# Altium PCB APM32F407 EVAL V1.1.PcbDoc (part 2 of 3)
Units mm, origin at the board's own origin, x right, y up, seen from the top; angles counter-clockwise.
Board outline 133.48 x 125.98 mm, 2 copper layers (Top Layer, Bottom Layer); 143 components, 208 nets, 809 pads, 486 vias.
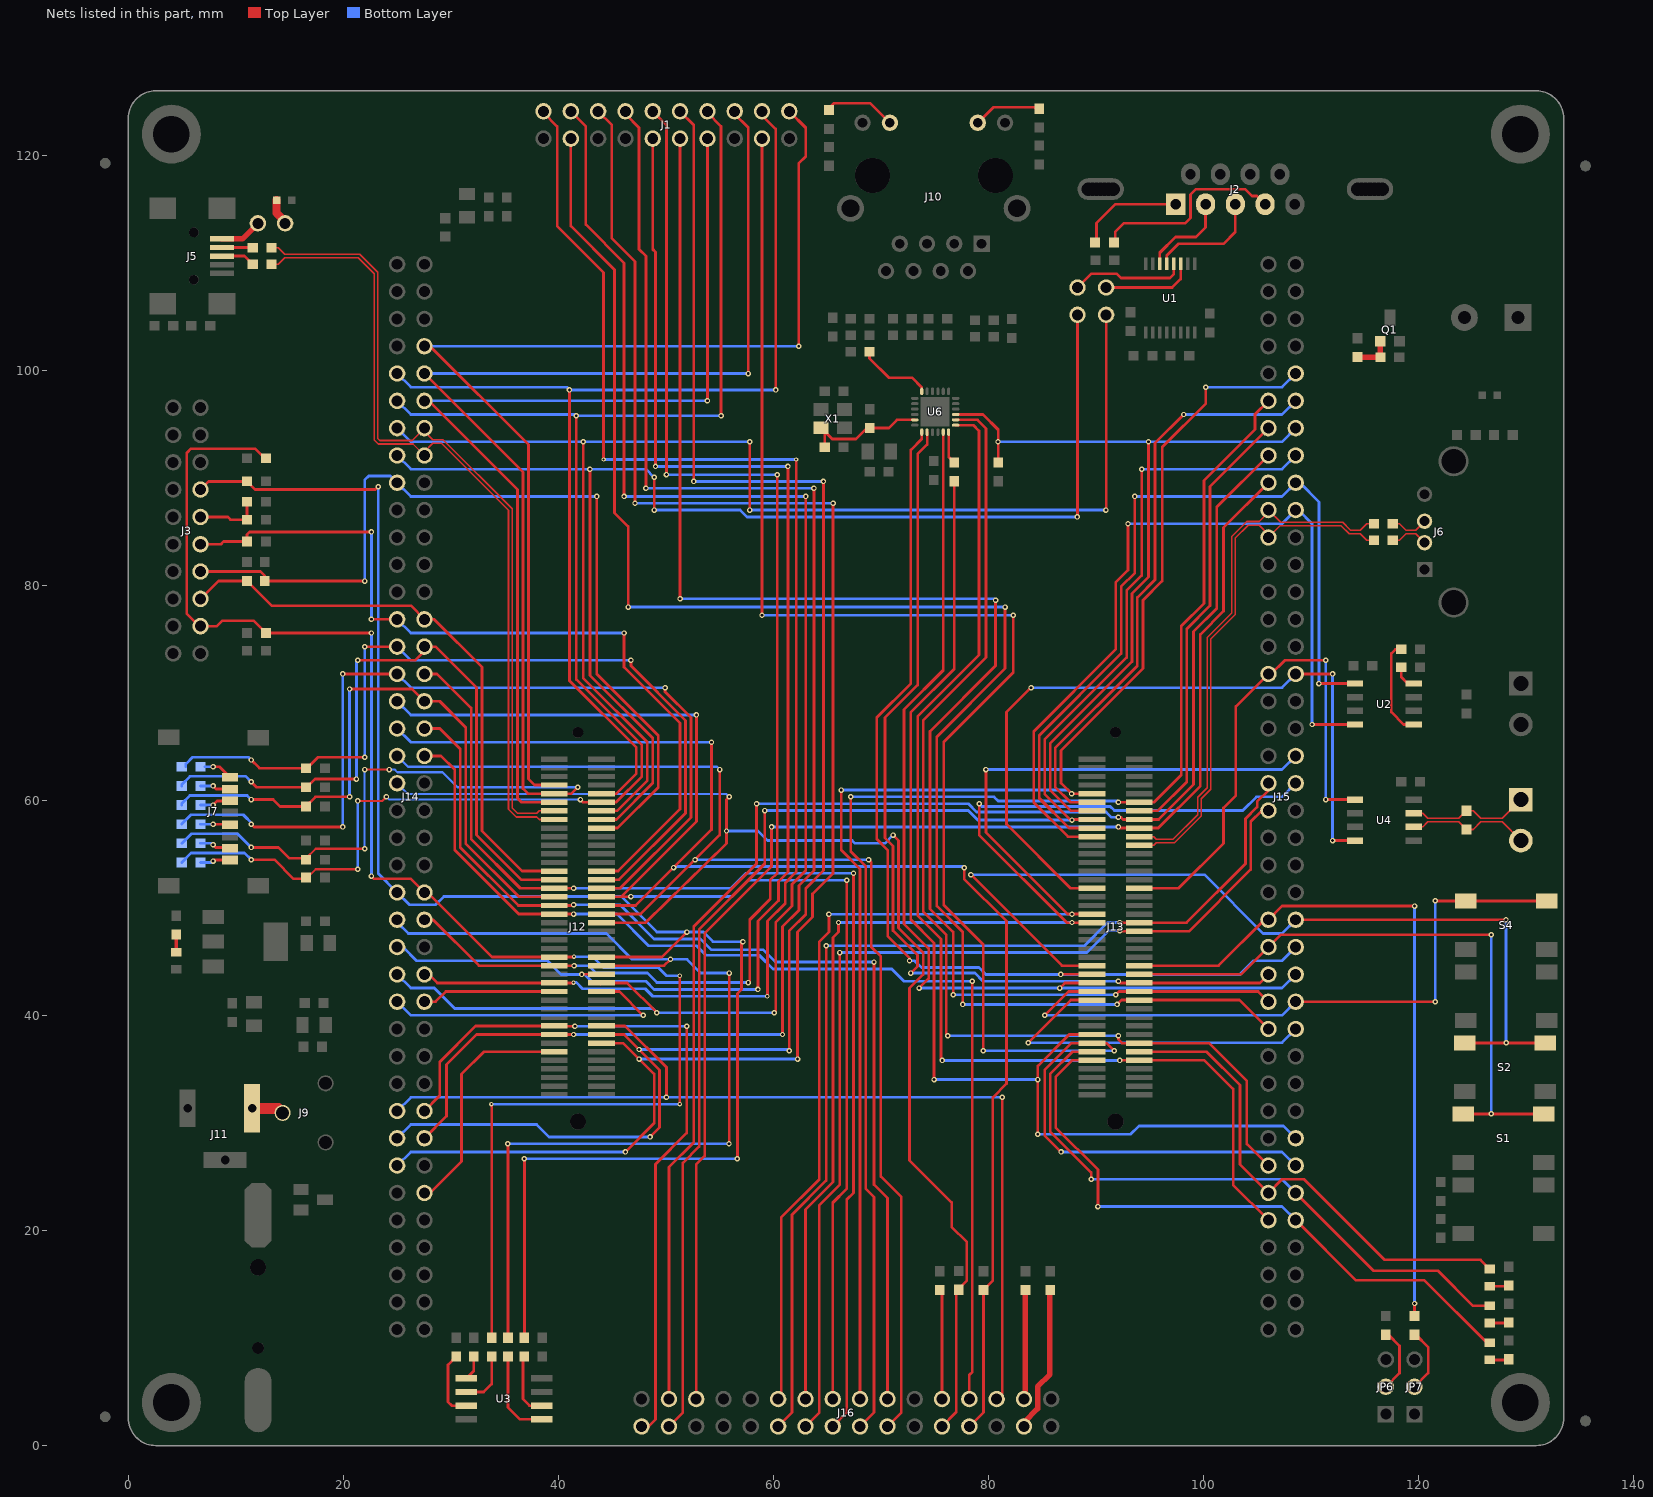
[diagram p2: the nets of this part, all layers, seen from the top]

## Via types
v1: diameter 0.508, hole 0.254, Top Layer to Bottom Layer, 294 vias
v2: diameter 0.61, hole 0.305, Top Layer to Bottom Layer, 172 vias
v3: diameter 0.406, hole 0.203, Top Layer to Bottom Layer, 17 vias
v4: diameter 0.6, hole 0.3, Top Layer to Bottom Layer, 3 vias

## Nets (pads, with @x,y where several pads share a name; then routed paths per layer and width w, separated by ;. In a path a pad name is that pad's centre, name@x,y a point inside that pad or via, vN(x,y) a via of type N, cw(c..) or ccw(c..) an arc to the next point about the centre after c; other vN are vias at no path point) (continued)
NetC32_2: C32.2 R40.1 U6.5 X1.3 | length 10.9
  Top Layer w0.254: C32.2@64.76,92.837 64.76,94.302 65.463,93.599 67.667,93.599 68.697,94.629 R40.1@68.937,94.629 70.729,94.629 71.489,95.389 U6.5@73.133,95.389
NetD1_1: D1.1 R59.2 | length 1.6
  Top Layer w0.3: D1.1@4.445,45.885 R59.2@4.445,47.512
NetD2_1: D2.1 JP1.1 | length 2.5
  Top Layer w0.762: D2.1@13.778,115.824 13.778,114.619 14.581,113.816 JP1.1@14.581,113.665
NetD4_1: D4.1 R23.2 | length 1.8
  Top Layer w0.254: D4.1@126.595,11.392 128.321,11.392 R23.2@128.373,11.444
NetD5_1: D5.1 R24.2 | length 1.8
  Top Layer w0.254: D5.1@126.595,14.821 128.321,14.821 R24.2@128.373,14.873
NetD6_1: D6.1 R22.2 | length 1.8
  Top Layer w0.254: D6.1@126.595,7.963 128.321,7.963 R22.2@128.373,8.015
NetJ2_1: J2.1 R8.1 | length 9.9
  Top Layer w0.254: R8.1@90.033,111.887 90.033,113.679 91.797,115.443 J2.1@97.409,115.443
NetJ2_4: J2.4 R8.2 | length 18.4
  Top Layer w0.254: R8.2@91.783,111.887 91.783,112.889 92.559,113.665 98.274,113.665 98.782,114.173 98.782,116.332 99.29,116.84 103.862,116.84 104.497,116.205 104.953,116.205 J2.4@105.715,115.443
NetJ3_11: J3.11 R5.1 R21.2 | length 6.1
  Top Layer w0.254: J3.11@6.707,86.36 9.247,86.36 9.501,86.106 R21.2@11.039,86.106 R5.1@11.039,87.757
NetJ5_1: J5.1 JP1.2 | length 3.9
  Top Layer w0.508: J5.1@8.695,112.217 10.593,112.217 JP1.2@12.041,113.665
NetJ5_2: J5.2 R45.2 | length 2.9
  Top Layer w0.254: J5.2@8.695,111.417 11.533,111.417 R45.2@11.571,111.379
NetJ5_3: J5.3 R49.2 | length 3.2
  Top Layer w0.254: J5.3@8.695,110.617 10.809,110.617 R49.2@11.571,109.855
NetJ6_2: J6.2 R7.2 | length 3.6
  Top Layer w0.152: R7.2@117.588,84.201 118.213,84.201 118.81,84.798 119.711,84.798 J6.2@120.546,83.963
NetJ6_3: J6.3 R14.2 | length 3.6
  Top Layer w0.152: R14.2@117.588,85.725 118.213,85.725 118.81,85.128 119.711,85.128 J6.3@120.546,85.963
NetJ7_1: J7.1 R55.1 | length 2.8
  Top Layer w0.254: v1(7.874,63.119) 8.496,63.119 J7.1@9.465,62.15
  Bottom Layer w0.254: R55.1@7.098,63.119 v1(7.874,63.119)
NetJ7_2: J7.2 R48.1 | length 2.9
  Top Layer w0.254: v1(7.874,61.341) 8.165,61.05 J7.2@9.465,61.05
  Bottom Layer w0.254: R48.1@6.717,61.341 v1(7.874,61.341)
NetJ7_3: J7.3 R57.1 | length 2.9
  Top Layer w0.254: v1(7.874,59.563) 8.261,59.95 J7.3@9.465,59.95
  Bottom Layer w0.254: R57.1@6.717,59.563 v1(7.874,59.563)
NetJ7_5: J7.5 R56.1 | length 2.8
  Top Layer w0.254: v1(7.874,57.785) 9.43,57.785 J7.5@9.465,57.75
  Bottom Layer w0.254: R56.1@6.717,57.785 v1(7.874,57.785)
NetJ7_7: J7.7 R10.1 | length 2.9
  Top Layer w0.254: v1(7.874,55.88) 8.128,55.626 9.389,55.626 J7.7@9.465,55.55
  Bottom Layer w0.254: R10.1@6.717,56.007 7.747,56.007 v1(7.874,55.88)
NetJ7_8: J7.8 R19.1 | length 2.8
  Top Layer w0.254: v1(7.874,54.356) 7.968,54.45 J7.8@9.465,54.45
  Bottom Layer w0.254: R19.1@6.717,54.229 7.747,54.229 v1(7.874,54.356)
NetJ8_1: J8.1 R27.1 U4.7 | length 11.5
  Top Layer w0.152: U4.7@119.541,58.801 120.372,58.801 120.842,58.331 123.726,58.331 R27.1@124.436,59.041 125.071,59.041 125.781,58.331 127.76,58.331 J8.1@129.5,60.071
NetJ8_2: J8.2 R27.2 U4.6 | length 11.5
  Top Layer w0.152: U4.6@119.541,57.531 120.372,57.531 120.842,58.001 123.726,58.001 R27.2@124.436,57.291 125.071,57.291 125.781,58.001 127.76,58.001 J8.2@129.5,56.261
NetJ9_1: J9.1 J11.4 | length 3
  Top Layer w1.016: J11.4@11.509,31.356 13.936,31.356 J9.1@14.351,30.941
NetJ10_10: J10.10 R37.1 | length 6.3
  Top Layer w0.254: J10.10@78.991,123.01 80.441,124.46 84.29,124.46 R37.1@84.558,124.192
NetJ10_11: J10.11 R38.1 | length 7
  Top Layer w0.254: R38.1@64.873,124.065 65.649,124.841 68.99,124.841 J10.11@70.821,123.01
NetJ16_23: J16.23 R44.2 | length 10.2
  Top Layer w0.254: R44.2@75.462,14.467 75.668,14.261 J16.23@75.668,4.318
NetJ16_29: J16.29 R46.2 | length 10.2
  Top Layer w0.508: J16.29@83.288,4.318 83.415,4.445 83.415,14.443 R46.2@83.439,14.467
NetJ16_30: J16.30 R47.1 | length 13.7
  Top Layer w0.508: J16.30@83.288,1.778 83.288,2.159 84.558,3.429 84.558,5.475 85.701,6.618 85.701,14.443 R47.1@85.725,14.467
NetJP4_1: JP4.1 U1.11 | length 8.7
  Top Layer w0.254: JP4.1@90.932,107.696 97.075,107.696 97.865,108.486 U1.11@97.865,109.905
NetJP5_1: JP5.1 U1.12 | length 10.8
  Top Layer w0.254: JP5.1@88.265,107.696 89.535,108.966 91.924,108.966 92.305,108.585 96.877,108.585 97.215,108.923 U1.12@97.215,109.905
NetJP6_2: JP6.2 R61.1 | length 6
  Top Layer w0.254: JP6.2@116.943,5.461 118.213,6.731 118.213,9.271 117.183,10.301 R61.1@116.943,10.301
NetJP7_2: JP7.2 R62.1 | length 6
  Top Layer w0.254: JP7.2@119.61,5.461 120.88,6.731 120.88,9.144 119.723,10.301 R62.1@119.61,10.301
NetQ1_B: Q1.B R25.1 R28.2 | length 3.6
  Top Layer w0.508: R25.1@114.3,101.233 114.314,101.219 R28.2@116.449,101.219 116.424,101.244 Q1.B@116.424,102.686
NetR9_1: R9.1 U3.3 | length 6.4
  Top Layer w0.254: R9.1@30.48,8.269 29.718,7.507 29.718,4.064 30.075,3.707 U3.3@31.425,3.707
NetR11_2: R11.2 U2.5 | length 9.1
  Top Layer w0.254: R11.2@118.378,74.041 117.832,74.041 117.451,73.66 117.451,68.199 118.594,67.056 U2.5@119.541,67.056
NetR12_1: R12.1 U3.5 | length 8.3
  Top Layer w0.254: R12.1@35.306,8.269 35.306,3.556 36.425,2.437 U3.5@38.425,2.437
NetR15_2: R15.2 U3.2 | length 5.2
  Top Layer w0.254: U3.2@31.425,4.977 33.044,4.977 33.782,5.715 R15.2@33.782,8.269
NetR16_1: R16.1 U3.1 | length 2.3
  Top Layer w0.254: U3.1@31.425,6.247 32.131,6.953 R16.1@32.131,8.269
NetR17_1: R17.1 U3.6 | length 6
  Top Layer w0.254: R17.1@36.83,8.269 36.703,8.142 36.703,4.318 37.314,3.707 U3.6@38.425,3.707
NetR18_2: R18.2 U2.8 | length 2.3
  Top Layer w0.254: R18.2@118.378,72.39 118.378,71.463 118.975,70.866 U2.8@119.541,70.866
NetR30_1: R30.1 U6.12 | length 3
  Top Layer w0.254: U6.12@76.283,94.239 76.283,91.954 R30.1@76.811,91.426
NetR41_1: R41.1 U6.24 | length 7
  Top Layer w0.254: R41.1@68.923,101.727 68.923,101.106 70.715,99.314 72.874,99.314 73.783,98.405 U6.24@73.783,98.039
PA0_CAMRE_PW: J1.3 J13.68 J15.68 | length 163
  Top Layer w0.254: v1(58.928,77.216) J1.3@58.928,121.539 ; v1(79.502,36.703) 79.502,46.609 75.819,50.292 75.819,65.405 82.296,71.882 v1(82.296,77.216) ; v1(86.741,27.305) 85.217,28.829 85.217,34.925 87.716,37.424 J13.68@89.605,37.424 90.973,37.424 v1(91.694,36.703)
  Bottom Layer w0.254: v1(58.928,77.216) v1(82.296,77.216) ; v1(79.502,36.703) v1(91.694,36.703) ; v1(86.741,27.305) 107.291,27.305 J15.68@108.561,26.035
PA1_RMII_REF_CLK: J13.67 J15.67 U6.14 | length 101.5
  Top Layer w0.254: v1(76.2,38.1) 76.073,38.227 76.073,47.498 73.914,49.657 73.914,67.437 79.756,73.279 79.756,94.591 78.958,95.389 U6.14@76.933,95.389 ; v1(92.075,38.1) 92.075,37.763 92.415,37.424 J13.67@94.005,37.424 100.498,37.424 104.013,33.909 104.013,28.043 J15.67@106.021,26.035
  Bottom Layer w0.254: v1(76.2,38.1) v1(92.075,38.1)
PA2_ETH_MDIO: J13.66 J15.66 R30.2 | length 105.2
  Top Layer w0.254: v1(74.93,34.036) 74.93,46.736 72.771,48.895 72.771,68.199 76.811,72.239 R30.2@76.811,89.676 ; v1(84.582,28.956) v1(84.582,34.036) 84.582,35.306 87.5,38.224 J13.66@89.605,38.224
  Bottom Layer w0.254: v1(74.93,34.036) v1(84.582,34.036) ; v1(84.582,28.956) 93.218,28.956 93.98,29.718 107.418,29.718 J15.66@108.561,28.575
PA3_SDR_CKE: J13.58 J15.58 | length 32.9
  Top Layer w0.254: v1(83.693,37.465) 87.652,41.424 J13.58@89.605,41.424
  Bottom Layer w0.254: v1(83.693,37.465) 107.291,37.465 J15.58@108.561,38.735
PA4_DCMI_HS: J1.17 J13.57 J15.57 | length 151.1
  Top Layer w0.254: J1.17@41.148,121.539 41.148,113.411 45.212,109.347 45.212,86.741 46.482,85.471 v1(46.482,77.978) ; v1(77.597,41.021) 77.597,47.752 75.184,50.165 75.184,65.913 81.534,72.263 v1(81.534,77.978) ; v1(91.948,41.021) 92.351,41.424 J13.57@94.005,41.424 103.332,41.424 J15.57@106.021,38.735
  Bottom Layer w0.254: v1(46.482,77.978) v1(81.534,77.978) ; v1(77.597,41.021) v1(91.948,41.021)
PA5_KEY4: J13.56 J15.56 S4.3 S4.4 | length 61.9
  Top Layer w0.254: v1(85.217,40.005) 87.436,42.224 J13.56@89.605,42.224 ; J15.56@108.561,41.275 v1(121.539,41.275) ; v1(121.539,50.673) 121.575,50.637 S4.4@124.393,50.637 S4.3@131.893,50.637
  Bottom Layer w0.254: v1(85.217,40.005) 107.291,40.005 J15.56@108.561,41.275 ; v1(121.539,41.275) v1(121.539,50.673)
PA6_DCMI_PIXCK: J1.9 J13.55 J15.55 | length 142.1
  Top Layer w0.254: v1(51.308,78.74) J1.9@51.308,121.539 ; v1(76.708,41.91) 76.708,47.752 74.549,49.911 74.549,66.421 80.645,72.517 v1(80.645,78.613) ; v1(91.821,41.91) 92.135,42.224 J13.55@94.005,42.224 105.072,42.224 J15.55@106.021,41.275
  Bottom Layer w0.254: v1(51.308,78.74) 80.518,78.74 v1(80.645,78.613) ; v1(76.708,41.91) v1(91.821,41.91)
PA7_RMII_CRS_DV: J13.54 J15.54 U6.11 | length 93.3
  Top Layer w0.254: v1(73.533,42.545) 74.422,43.434 74.422,46.228 72.136,48.514 72.136,68.453 75.783,72.1 U6.11@75.783,94.239 ; v1(86.614,42.545) 87.093,43.024 J13.54@89.605,43.024
  Bottom Layer w0.254: v1(73.533,42.545) v1(86.614,42.545) 107.291,42.545 J15.54@108.561,43.815
PA8_CAMER_XCLK: J1.7 J12.12 J14.12 | length 95
  Top Layer w0.254: J14.12@27.535,97.155 27.94,97.155 36.195,88.9 36.195,60.198 36.569,59.824 J12.12@39.605,59.824 ; v1(53.848,97.155) J1.7@53.848,121.539
  Bottom Layer w0.254: J14.12@27.535,97.155 v1(53.848,97.155)
PA9_USART1_TX: J12.13 J14.13 JP4.2 | length 130.4
  Top Layer w0.254: v1(42.291,93.345) 42.291,71.374 48.26,65.405 48.26,61.849 45.435,59.024 J12.13@44.005,59.024 ; v1(57.785,86.995) v1(57.785,93.345) ; v1(90.908,86.995) 90.932,87.019 JP4.2@90.932,105.156
  Bottom Layer w0.254: J14.13@24.995,94.615 26.265,93.345 v1(42.291,93.345) v1(57.785,93.345) ; v1(57.785,86.995) v1(90.908,86.995)
PA10_USART1_RX: J12.15 J14.15 JP5.2 | length 124
  Top Layer w0.254: v1(42.926,90.805) 42.926,71.628 48.768,65.786 48.768,61.595 45.397,58.224 J12.15@44.005,58.224 ; v1(48.895,86.995) v1(48.895,90.043) ; v1(88.241,86.36) 88.265,86.384 JP5.2@88.265,105.156
  Bottom Layer w0.254: J14.15@24.995,92.075 26.265,90.805 v1(42.926,90.805) 48.133,90.805 v1(48.895,90.043) ; v1(48.895,86.995) 56.896,86.995 57.531,86.36 v1(88.241,86.36)
PA11_OTG_FS_N: J12.14 J14.14 R45.1 | length 74.6
  Top Layer w0.152: R45.1@13.321,111.379 13.946,111.379 14.543,110.782 21.511,110.782 23.19,109.103 23.19,93.65 23.368,93.472 26.392,93.472 J14.14@27.535,94.615 27.535,94.334 28.321,93.548 29.261,93.548 35.687,87.122 35.687,59.297 36.195,58.789 37.968,58.789 38.203,59.024 J12.14@39.605,59.024
PA12_OTG_FS_P: J12.16 J14.16 R49.1 | length 74.7
  Top Layer w0.152: R49.1@13.321,109.855 13.946,109.855 14.543,110.452 21.374,110.452 22.86,108.966 22.86,93.513 23.135,93.239 23.231,93.142 26.468,93.142 J14.16@27.535,92.075 27.535,92.432 28.321,93.218 29.124,93.218 35.357,86.985 35.357,59.16 36.058,58.458 37.968,58.458 38.203,58.224 J12.16@39.605,58.224
PA13_SWDIO: J3.7 J12.17 J14.17 R3.1 | length 84.1
  Top Layer w0.254: J3.7@6.707,81.28 12.295,81.28 12.676,80.899 R3.1@12.676,80.405 12.69,80.391 v1(21.971,80.391) ; v1(43.561,88.265) 43.561,71.755 49.276,66.04 49.276,61.214 45.486,57.424 J12.17@44.005,57.424
  Bottom Layer w0.254: v1(21.971,80.391) 21.971,89.789 22.352,90.17 24.36,90.17 J14.17@24.995,89.535 26.265,88.265 v1(43.561,88.265)
PA14_SWCLK: J3.9 J12.27 J14.27 R20.2 | length 77.1
  Top Layer w0.254: J3.9@6.707,83.82 8.612,83.82 8.866,84.074 R20.2@11.039,84.074 11.039,84.723 11.279,84.963 v1(22.606,84.963) ; v1(22.606,76.835) J14.27@24.995,76.835 ; J12.27@44.005,53.424 45.55,53.424 51.308,59.182 51.308,67.183 46.101,72.39 v1(46.101,75.565)
  Bottom Layer w0.254: v1(22.606,76.835) v1(22.606,84.963) ; J14.27@24.995,76.835 26.265,75.565 v1(46.101,75.565)
PA15_TDI: J3.5 J12.28 J14.28 R2.1 | length 53.7
  Top Layer w0.254: J3.5@6.707,78.74 8.372,80.405 R2.1@11.025,80.405 13.325,78.105 26.265,78.105 J14.28@27.535,76.835 28.448,76.835 32.893,72.39 32.893,57.15 36.619,53.424 J12.28@39.605,53.424
PB0_KEY1: J13.51 J15.51 S1.3 S1.4 | length 58.4
  Top Layer w0.254: J13.51@94.005,43.824 103.49,43.824 J15.51@106.021,46.355 107.164,47.498 v1(126.746,47.498) ; S1.4@124.139,30.825 S1.3@131.639,30.825
  Bottom Layer w0.254: v1(126.746,30.861) v1(126.746,47.498)
PB1_KEY2: J13.50 J15.50 S2.3 S2.4 | length 86.2
  Top Layer w0.254: v1(78.359,53.086) 86.821,44.624 J13.50@89.605,44.624 ; J15.50@108.561,48.895 v1(128.119,48.895) ; S2.4@124.266,37.429 S2.3@131.766,37.429
  Bottom Layer w0.254: v1(78.359,53.086) 100.076,53.086 105.537,47.625 107.291,47.625 J15.50@108.561,48.895 ; v1(128.119,48.895) 128.119,37.489 v1(128.143,37.465)
PB2_BOOT1: J13.49 J15.49 R62.2 | length 66
  Top Layer w0.254: J13.49@94.005,44.624 101.393,44.624 105.664,48.895 J15.49@106.021,48.895 107.291,50.165 v1(119.61,50.165) ; R62.2@119.61,12.051 v1(119.61,13.208)
  Bottom Layer w0.254: v1(119.61,13.208) v1(119.61,50.165)
PB3_SPI_SCK: J3.13 J12.47 J14.47 R4.1 R17.2 | length 156.2
  Top Layer w0.254: J3.13@6.707,88.9 7.469,89.662 R4.1@11.039,89.662 11.039,89.648 11.787,88.9 22.987,88.9 v1(23.241,89.154) ; v1(36.806,26.67) 36.83,26.646 R17.2@36.83,10.019 ; J12.47@44.005,45.424 49.615,45.424 v1(51.943,47.752) ; v1@56.642,26.67 56.642,42.037 57.023,42.418 57.023,46.736 v1(57.15,46.863)
  Bottom Layer w0.254: v1(23.241,89.154) 23.241,53.189 J14.47@24.995,51.435 26.138,50.292 28.575,50.292 29.337,51.054 45.847,51.054 49.149,47.752 v1(51.943,47.752) 53.467,47.752 54.356,46.863 v1(57.15,46.863) ; v1(36.806,26.67) v1(56.618,26.67)
PB4_SPI_MISO: J3.3 J12.48 J14.48 R1.1 R6.2 R15.1 | length 147.5
  Top Layer w0.254: R6.2@12.662,91.821 11.773,92.71 5.818,92.71 5.437,92.329 5.437,77.343 6.58,76.2 J3.3@6.707,76.2 8.231,76.2 8.739,76.708 11.646,76.708 R1.1@12.789,75.565 v1(22.606,75.565) ; v1(22.606,52.959) 22.86,52.705 26.265,52.705 J14.48@27.535,51.435 27.813,51.435 33.824,45.424 J12.48@39.605,45.424 41.487,45.424 v3(41.444,45.466) ; v3(33.758,31.75) 33.782,31.726 R15.1@33.782,10.019 ; v3(51.284,31.75) v3(51.284,43.688)
  Bottom Layer w0.254: v1(22.606,52.959) v1(22.606,75.565) ; v3(33.758,31.75) v3(51.284,31.75) ; v3(41.444,45.466) 43.18,45.466 44.196,44.45 49.276,44.45 50.038,43.688 v3(51.284,43.688)
PB5_SPI_MOSI: J12.49 J14.49 R12.2 | length 94.5
  Top Layer w0.254: v1(35.282,28.067) 35.306,28.043 R12.2@35.306,10.019 ; J12.49@44.005,44.624 49.831,44.624 v1(50.419,45.212) ; v1@55.88,28.067 v1(55.88,43.942)
  Bottom Layer w0.254: J14.49@24.765,48.895 J14.49@24.995,48.895 24.995,48.665 26.035,47.625 44.45,47.625 46.863,45.212 v1(50.419,45.212) 51.943,45.212 53.213,43.942 v1(55.88,43.942) ; v1(35.282,28.067) v1(55.856,28.067)
PB6_DCMI_D5: J1.12 J12.50 J14.50 | length 125.5
  Top Layer w0.254: J14.50@27.535,48.895 28.321,48.895 32.592,44.624 J12.50@39.605,44.624 v1(41.449,44.624) ; J1.12@48.768,124.079 50.038,122.809 v1(50.038,90.297) ; v1(57.658,43.053) 57.785,43.18 57.785,48.895 59.69,50.8 59.69,52.578 60.35,53.238 v1(60.35,90.272) v1@60.325,90.297
  Bottom Layer w0.254: v1(41.449,44.624) 42.799,44.624 43.481,43.942 48.26,43.942 49.149,43.053 v1(57.658,43.053) ; v1@50.038,90.272 v1(60.35,90.272)
PB7_DCMI_VS: J1.11 J12.51 J14.51 | length 129.7
  Top Layer w0.254: v1(42.164,43.815) 42.173,43.824 J12.51@44.005,43.824 ; J1.11@48.768,121.539 48.768,111.252 49.022,110.998 v1(49.022,91.059) ; v1(58.547,42.418) 58.547,48.768 60.452,50.673 60.452,52.451 61.341,53.34 v1(61.341,91.059)
  Bottom Layer w0.254: J14.51@24.995,46.355 25.527,46.355 26.797,45.085 38.965,45.085 40.235,43.815 v1(42.164,43.815) 42.418,43.815 43.053,43.18 48.133,43.18 48.895,42.418 v1(58.547,42.418) ; v1(49.022,91.059) v1(61.341,91.059)
PB8_I2C1_SCL: J1.18 J12.53 J14.53 | length 146.9
  Top Layer w0.254: J1.18@41.148,124.079 42.545,122.682 42.545,113.538 46.101,109.982 v1(46.101,88.265) ; J12.53@43.907,42.926 J12.53@44.005,43.024 46.384,43.024 v1(49.149,40.259) ; v1(60.071,40.259) 60.198,40.386 60.198,48.641 61.722,50.165 61.722,52.197 62.992,53.467 v1(62.992,88.265)
  Bottom Layer w0.254: J14.53@24.995,43.815 26.265,42.545 28.448,42.545 30.353,40.64 48.768,40.64 v1(49.149,40.259) v1(60.071,40.259) ; v1(46.101,88.265) v1(62.992,88.265)
PB9_I2C1_SDA: J1.20 J12.54 J14.54 | length 136.4
  Top Layer w0.254: J14.54@27.535,43.815 27.94,43.815 28.731,43.024 J12.54@39.605,43.024 41.373,43.024 v3(41.402,43.053) ; J1.20@38.608,124.079 38.608,123.952 39.878,122.682 39.878,113.411 44.196,109.093 v3(44.196,91.694) ; v3@59.436,41.783 59.436,48.768 61.087,50.419 61.087,52.324 62.103,53.34 v3(62.103,91.694)
  Bottom Layer w0.254: v3(41.402,43.053) 41.656,43.053 42.227,42.481 48.069,42.481 48.768,41.783 v3(59.412,41.783) ; v3(44.196,91.694) v3(62.103,91.694)
PB10_USART3_TX: J13.32 J15.32 U4.4 | length 70.2
  Top Layer w0.254: v1(83.947,70.485) 81.661,68.199 81.661,57.785 87.622,51.824 J13.32@89.605,51.824 ; J15.32@108.561,71.755 v1(111.99,71.755) ; v1(111.99,56.261) U4.4@114.091,56.261
  Bottom Layer w0.254: v1(83.947,70.485) 107.291,70.485 J15.32@108.561,71.755 ; v1(111.99,56.261) v1(111.99,71.755)
PB11_USART3_RX: J13.31 J15.31 U4.1 | length 48.6
  Top Layer w0.254: J13.31@94.005,51.824 97.671,51.824 101.854,56.007 101.854,59.309 102.997,60.452 102.997,68.731 J15.31@106.021,71.755 106.275,71.755 107.545,73.025 v1(111.355,73.025) ; v1(111.355,60.071) U4.1@114.091,60.071
  Bottom Layer w0.254: v1(111.355,60.071) v1(111.355,73.025)
PB12_CAN2_RX: J13.20 J15.20 U2.4 | length 77.1
  Top Layer w0.254: J13.20@89.605,56.624 87.394,56.624 84.201,59.817 84.201,66.421 91.821,74.041 91.821,80.264 92.964,81.407 v1(92.964,85.725) ; v1(110.085,67.056) U2.4@114.091,67.056
  Bottom Layer w0.254: v1(92.964,85.725) 107.291,85.725 J15.20@108.561,86.995 108.815,86.995 110.085,85.725 v1(110.085,67.056)
PB13_CAN2_TX: J13.18 J15.18 U2.1 | length 76.4
  Top Layer w0.254: J13.18@89.605,57.424 87.483,57.424 84.709,60.198 84.709,66.04 92.329,73.66 92.329,79.883 93.599,81.153 v1(93.599,88.265) ; v1(110.72,70.866) U2.1@114.091,70.866
  Bottom Layer w0.254: v1(93.599,88.265) 107.291,88.265 J15.18@108.561,89.535 108.942,89.535 110.72,87.757 v1(110.72,70.866)
PB14_OTG_HS_N: J13.21 J15.21 R7.1 | length 49.1
  Top Layer w0.152: J13.21@94.005,55.824 95.353,55.824 95.588,56.058 97.292,56.058 99.771,58.537 99.771,60.147 100.66,61.036 100.66,75.006 102.946,77.292 102.946,84.404 104.14,85.598 105.156,85.598 106.021,84.733 J15.21@106.021,84.455 107.088,85.522 112.804,85.522 113.528,84.798 114.568,84.798 115.165,84.201 R7.1@115.838,84.201
PB15_OTG_HS_P: J13.19 J15.19 R14.1 | length 49
  Top Layer w0.152: J13.19@94.005,56.624 95.353,56.624 95.588,56.389 97.156,56.389 99.441,58.674 99.441,60.284 100.33,61.173 100.33,75.143 102.616,77.429 102.616,84.541 104.003,85.928 105.156,85.928 106.021,86.793 J15.19@106.021,86.895 ; J15.19@106.021,86.995 107.164,85.852 112.941,85.852 113.665,85.128 114.568,85.128 115.165,85.725 R14.1@115.838,85.725
  Top Layer w0.254: J15.19@106.021,86.895 J15.19@106.021,86.995
PC0_LED1: D6.2 J13.72 J15.72 | length 59.4
  Top Layer w0.254: J13.72@89.605,35.824 87.767,35.824 86.233,34.29 86.233,29.591 90.17,25.654 v1(90.17,22.225) ; J15.72@108.561,20.955 114.149,15.367 120.523,15.367 126.327,9.563 D6.2@126.595,9.563
  Bottom Layer w0.254: v1(90.17,22.225) 107.291,22.225 J15.72@108.561,20.955
PC1_ETH_MDC: J13.71 J15.71 U6.13 | length 105.9
  Top Layer w0.254: v1(75.692,35.814) 75.565,35.941 75.565,47.117 73.406,49.276 73.406,67.818 79.097,73.509 79.097,94.361 78.569,94.889 U6.13@76.933,94.889 ; v1(92.202,35.814) 92.212,35.824 J13.71@94.005,35.824 100.066,35.824 102.743,33.147 102.743,24.233 J15.71@106.021,20.955
  Bottom Layer w0.254: v1(75.692,35.814) v1(92.202,35.814)
PC2_LED2: D4.2 J13.70 J15.70 | length 58
  Top Layer w0.254: v1(89.535,24.765) 89.535,25.4 85.725,29.21 85.725,34.544 87.805,36.624 J13.70@89.605,36.624 ; J15.70@108.561,23.495 115.8,16.256 121.793,16.256 125.057,12.992 D4.2@126.595,12.992
  Bottom Layer w0.254: v1(89.535,24.765) 107.291,24.765 J15.70@108.561,23.495
PC3_LED3: D5.2 J13.69 J15.69 | length 46.3
  Top Layer w0.254: J13.69@94.005,36.624 100.282,36.624 103.378,33.528 103.378,26.138 J15.69@106.021,23.495 107.291,24.765 109.347,24.765 116.84,17.272 125.744,17.272 D5.2@126.595,16.421
PC4_RMII_RXD0: J13.53 J15.53 U6.8 | length 87.4
  Top Layer w0.254: v1(72.771,43.942) 73.381,44.552 73.381,45.618 71.12,47.879 71.12,55.753 70.358,56.515 70.358,67.691 73.406,70.739 73.406,92.202 74.283,93.079 U6.8@74.283,94.239 ; v1(92.075,43.18) 92.231,43.024 J13.53@94.005,43.024 105.23,43.024 J15.53@106.021,43.815
  Bottom Layer w0.254: v1(72.771,43.942) 78.716,43.942 79.478,43.18 v1(92.075,43.18)
PC5_RMII_RXD1: J13.52 J15.52 U6.7 | length 92.5
  Top Layer w0.254: v1(72.644,45.085) 72.644,45.339 70.612,47.371 70.612,55.372 69.596,56.388 69.596,67.691 72.771,70.866 72.771,92.583 73.783,93.595 U6.7@73.783,94.239 ; v1@86.732,43.824 J13.52@89.605,43.824
  Bottom Layer w0.254: v1(72.644,45.085) 73.128,45.085 73.763,44.45 79.097,44.45 79.732,43.815 v1(86.717,43.815) 103.354,43.815 104.624,45.085 107.291,45.085 J15.52@108.561,46.355
PC6_DCMI_D0: J1.2 J12.8 J14.8 | length 104.7
  Top Layer w0.254: J14.8@27.535,102.235 28.067,102.235 37.211,93.091 37.211,61.976 37.763,61.424 J12.8@39.605,61.424 ; J1.2@61.468,124.079 62.992,122.555 62.992,119.888 62.333,119.229 v1(62.333,102.235)
  Bottom Layer w0.254: J14.8@27.535,102.235 v1(62.333,102.235)
PC7_DCMI_D1: J1.4 J12.9 J14.9 | length 104.5
  Top Layer w0.254: v1(41.021,98.171) 41.021,71.12 47.244,64.897 47.244,62.484 45.384,60.624 J12.9@44.005,60.624 ; J1.4@58.928,124.079 58.928,123.698 60.198,122.428 v1(60.198,98.171)
  Bottom Layer w0.254: J14.9@24.995,99.695 26.265,98.425 40.767,98.425 v1(41.021,98.171) v1(60.198,98.171)
PC8_SDIO_D0: J1.6 J12.10 J14.10 R10.2 R54.1 | length 150
  Top Layer w0.203: R54.1@16.524,54.483 16.524,54.61 17.413,55.499 v1(21.971,55.499) ; v1(21.971,62.865) v1(24.257,62.865)
  Top Layer w0.254: v1(11.43,55.626) 13.97,55.626 14.986,54.61 R54.1@16.524,54.61 ; J14.10@27.535,99.695 36.703,90.527 36.703,61.087 37.166,60.624 J12.10@39.605,60.624 41.193,60.624 v1(41.783,61.214) ; J1.6@56.388,124.079 56.388,123.825 57.658,122.555 v1(57.658,99.695)
  Bottom Layer w0.203: v1(21.971,55.499) v1(21.971,62.865) ; v1(24.257,62.865) 24.765,62.865 25.019,62.611 29.21,62.611 30.607,61.214 v1(41.783,61.214)
  Bottom Layer w0.254: R10.2@4.967,56.007 5.856,56.896 10.16,56.896 v1(11.43,55.626) ; J14.10@27.178,99.695 J14.10@27.535,99.695 v1(57.658,99.695)
PC9_SDIO_D1: J1.8 J12.11 J14.11 R19.2 R53.1 | length 147.8
  Top Layer w0.203: R53.1@16.524,52.705 17.413,53.594 v1(21.336,53.594) ; v1(21.336,59.944) 23.622,59.944 v1(24.003,60.325)
  Top Layer w0.254: v1(11.43,54.483) 13.589,54.483 15.367,52.705 R53.1@16.524,52.705 ; v1(41.656,95.758) 41.656,71.247 47.752,65.151 47.752,62.23 45.346,59.824 J12.11@44.005,59.824 42.284,59.824 v1(42.037,60.071) ; J1.8@53.848,124.079 53.848,123.952 55.118,122.682 v1(55.118,95.758)
  Bottom Layer w0.203: v1(21.336,53.594) v1(21.336,59.944) ; v1(24.003,60.325) 24.257,60.071 v1(42.037,60.071)
  Bottom Layer w0.254: R19.2@4.967,54.229 5.842,55.104 10.809,55.104 v1(11.43,54.483) ; J14.11@24.995,97.155 26.265,95.885 41.529,95.885 v1(41.656,95.758) v1(55.118,95.758)
PC10_SDIO_D2: J12.29 J14.29 R52.1 R55.2 | length 80.3
  Top Layer w0.254: v1(11.43,63.754) 12.192,62.992 R52.1@16.524,62.992 16.637,62.992 17.653,64.008 v1(21.971,64.008) ; v1(21.971,74.295) J14.29@24.995,74.295 ; J12.29@44.005,52.624 45.639,52.624 51.816,58.801 51.816,67.437 46.736,72.517 v1(46.736,73.025)
  Bottom Layer w0.254: R55.2@5.348,63.119 5.348,63.387 5.969,64.008 11.176,64.008 v1(11.43,63.754) ; v1(21.971,64.008) v1(21.971,74.295) ; J14.29@24.995,74.295 26.265,73.025 v1(46.736,73.025)
PC11_SDIO_D3: J12.30 J14.30 R48.2 R51.1 | length 64.7
  Top Layer w0.254: v1(11.43,61.722) 11.938,61.214 R51.1@16.524,61.214 ; R51.1@16.434,61.05 17.36,61.976 v1(21.209,61.976) ; v1(21.336,73.025) 26.67,73.025 27.535,73.89 J14.30@27.535,74.295 28.575,74.295 32.385,70.485 32.385,56.769 36.53,52.624 J12.30@39.605,52.624
  Bottom Layer w0.254: R48.2@4.967,61.341 4.967,61.482 5.715,62.23 10.922,62.23 v1(11.43,61.722) ; v1(21.209,61.976) 21.209,72.898 v1(21.336,73.025)
PC12_SDIO_CLK: J12.31 J14.31 R56.2 | length 84.8
  Top Layer w0.254: v1@11.465,57.75 11.684,57.531 v1(19.939,57.531) ; v1(19.939,71.755) J14.31@24.995,71.755 ; J12.31@44.005,51.824 45.728,51.824 52.324,58.42 52.324,67.691 49.911,70.104 v1(49.911,70.485)
  Bottom Layer w0.254: R56.2@4.967,57.785 5.842,58.66 10.682,58.66 11.557,57.785 v1(11.43,57.785) ; v1(19.939,57.531) v1(19.939,71.755) ; J14.31@24.995,71.755 26.265,70.485 v1(49.911,70.485)
PC13: J12.70 J14.70 | length 22.3
  Top Layer w0.254: J14.70@27.535,23.495 28.067,23.495 30.988,26.416 30.988,34.544 33.068,36.624 J12.70@39.605,36.624
PC_RX: J2.3 U1.13 | length 10.6
  Top Layer w0.254: U1.13@96.565,109.905 96.565,110.686 97.639,111.76 101.83,111.76 102.946,112.876 J2.3@102.946,115.443
PC_TX: J2.2 U1.14 | length 8.4
  Top Layer w0.254: U1.14@95.915,109.905 95.915,110.925 97.385,112.395 99.29,112.395 100.178,113.283 J2.2@100.178,115.443
PD0_SMC_D2: J12.32 J14.32 J16.16 | length 108.1
  Top Layer w0.254: J14.32@27.535,71.755 28.702,71.755 31.877,68.58 31.877,56.388 36.441,51.824 J12.32@39.605,51.824 41.394,51.824 v1(41.402,51.816) ; J16.16@65.508,1.778 66.802,3.072 66.802,22.86 67.437,23.495 v1(67.437,53.213)
  Bottom Layer w0.254: v1(41.402,51.816) 56.007,51.816 57.404,53.213 v1(67.437,53.213)
PD1_SMC_D3: J12.33 J14.33 J16.15 | length 120.4
  Top Layer w0.254: J12.33@44.005,51.024 45.817,51.024 ; v1(46.736,51.054) 46.706,51.024 45.817,51.024 ; v1(52.832,67.945) 52.832,58.039 45.817,51.024 ; J16.15@65.508,4.318 65.508,22.582 66.802,23.876 v1(66.802,52.578)
  Bottom Layer w0.254: J14.33@24.995,69.215 26.265,67.945 v1(52.832,67.945) ; v1(46.736,51.054) 56.134,51.054 57.658,52.578 v1(66.802,52.578)
PD2_SDIO_CMD: J12.34 J14.34 R50.1 R57.2 | length 60
  Top Layer w0.254: v1(11.43,60.071) 13.462,60.071 14.097,59.436 16.397,59.436 R50.1@16.524,59.309 ; R50.1@16.524,59.436 16.524,59.45 17.399,60.325 v1(20.574,60.325) ; v1(20.574,70.358) 26.392,70.358 J14.34@27.535,69.215 ; J14.34@27.813,69.215 28.956,69.215 31.369,66.802 31.369,56.007 36.352,51.024 J12.34@39.605,51.024
  Bottom Layer w0.254: R57.2@4.967,59.563 4.967,59.704 5.715,60.452 11.049,60.452 v1(11.43,60.071) ; v1(20.574,60.325) v1(20.574,70.358)
PD3_CTP_SDA: J12.35 J14.35 J16.26 R42.1 | length 133.2
  Top Layer w0.254: J12.35@44.005,50.224 47.176,50.224 v1(50.702,53.75) 54.229,57.277 v1(54.229,65.405) ; v1(77.724,53.721) 77.724,52.705 81.661,48.768 81.661,33.655 80.391,32.385 80.391,15.332 R42.1@79.526,14.467 79.526,3.072 78.232,1.778 J16.26@78.208,1.778
  Bottom Layer w0.254: J14.35@24.995,66.675 26.265,65.405 v1(54.229,65.405) ; v1(50.702,53.75) 50.8,53.848 77.597,53.848 v1(77.724,53.721)
PD4_LCD_RD: J12.36 J14.36 J16.19 | length 97.4
  Top Layer w0.254: J14.36@27.535,66.675 28.956,66.675 30.861,64.77 30.861,55.626 36.263,50.224 J12.36@39.605,50.224 41.334,50.224 v1(41.402,50.292) ; v1(69.342,44.958) 69.342,24.257 70.588,23.011 J16.19@70.588,4.318
  Bottom Layer w0.254: v1(41.402,50.292) 45.72,50.292 48.895,47.117 53.213,47.117 54.229,46.101 59.055,46.101 60.198,44.958 v1(69.342,44.958)
PD5_LCD_WR: J12.37 J14.37 J16.20 | length 121.3
  Top Layer w0.254: J12.37@44.005,49.424 47.646,49.424 v1(52.705,54.483) 54.991,56.769 v1(54.991,62.865) ; v1(68.834,54.483) 69.088,54.229 69.088,46.355 69.977,45.466 69.977,25.019 71.882,23.114 71.882,3.072 J16.20@70.588,1.778
  Bottom Layer w0.203: J14.37@24.995,64.135 26.011,63.119 54.737,63.119 v1(54.991,62.865)
  Bottom Layer w0.254: v1(52.705,54.483) v1(68.834,54.483)
PD6_CTP_RST: J12.38 J14.38 J16.25 | length 103
  Top Layer w0.254: J14.38@27.535,64.135 29.083,64.135 30.353,62.865 30.353,55.372 36.301,49.424 J12.38@39.605,49.424 v1(41.402,49.424) ; J16.25@78.208,4.318 78.208,6.58 78.486,6.858 v1(78.486,43.18)
  Bottom Layer w0.254: v1(41.402,49.424) 45.445,49.424 48.387,46.482 52.832,46.482 53.721,45.593 58.674,45.593 59.944,44.323 70.993,44.323 72.136,43.18 v1(78.486,43.18)
PD7_CTP_SCL: J12.39 J14.39 J16.24 R43.1 | length 126.6
  Top Layer w0.254: J12.39@44.005,48.624 48.116,48.624 55.626,56.007 v1(55.626,57.15) 55.626,60.071 v1(55.88,60.325) ; v1(71.12,56.769) 71.628,56.261 71.628,48.133 73.914,45.847 73.914,43.815 72.644,42.545 72.644,26.519 76.569,22.594 76.569,20.332 77.978,18.923 77.978,15.367 76.986,14.375 76.986,3.096 J16.24@75.668,1.778
  Bottom Layer w0.203: J14.39@24.995,61.595 26.011,60.579 55.626,60.579 v1(55.88,60.325)
  Bottom Layer w0.254: v1(55.626,57.15) 58.547,57.15 59.436,56.261 67.31,56.261 67.564,56.007 70.358,56.007 v1(71.12,56.769)
PD8_SMC_D13: J13.17 J15.17 J16.5 | length 128.5
  Top Layer w0.254: J16.5@52.808,4.318 52.808,26.138 53.594,26.924 53.594,47.625 59.817,53.848 v1(59.817,57.531) ; v1(92.075,57.531) 92.095,57.424 J13.17@94.005,57.424 95.778,57.424 99.695,61.341 99.695,75.438 101.854,77.597 101.854,85.368 J15.17@106.021,89.535
  Bottom Layer w0.254: v1(59.817,57.531) v1(92.075,57.531)
PD9_SMC_D14: J13.16 J15.16 J16.4 | length 144.1
  Top Layer w0.254: J16.4@50.268,1.778 51.562,3.072 51.562,26.289 53.086,27.813 53.086,48.006 59.182,54.102 v1(59.182,59.055) ; J13.16@89.605,58.224 87.572,58.224 85.217,60.579 85.217,65.659 92.837,73.279 92.837,79.502 94.234,80.899 v1(94.234,90.805)
  Bottom Layer w0.254: v1(59.182,59.055) 78.105,59.055 78.994,58.166 v1(87.757,58.166) ; v1(94.234,90.805) 107.291,90.805 J15.16@108.561,92.075
PD10_SDR_D10: J13.15 J15.15 J16.3 | length 135.2
  Top Layer w0.254: J16.3@50.268,4.318 50.268,25.884 52.578,28.194 52.578,48.26 58.42,54.102 v1(58.42,59.69) ; v1(92.075,58.42) 92.329,58.42 92.525,58.224 J13.15@94.005,58.224 ; J13.15@94.176,58.166 94.234,58.224 95.816,58.224 99.06,61.468 99.06,75.692 101.219,77.851 101.219,87.273 J15.15@106.021,92.075
  Bottom Layer w0.254: v1(58.42,59.69) 78.105,59.69 78.867,58.928 90.932,58.928 91.44,58.42 v1(92.075,58.42) ; J15.15@105.537,92.075 J15.15@106.021,92.075
PD11_ETH_RESET: J13.14 J15.14 R39.2 U6.15 | length 76.7
  Top Layer w0.254: U6.15@76.933,95.889 79.474,95.889 80.899,94.464 R39.2@80.899,91.426 ; J13.14@89.605,59.024 87.661,59.024 85.725,60.96 85.725,65.278 93.345,72.898 93.345,79.248 94.869,80.772 v1(94.869,93.345)
  Bottom Layer w0.254: v1(80.875,93.345) v1(94.869,93.345) 107.291,93.345 J15.14@108.561,94.615
PD12_SDR_D11: J13.13 J15.13 | length 41.6
  Top Layer w0.254: J13.13@94.005,59.024 95.727,59.024 98.425,61.722 98.425,75.946 100.584,78.105 100.584,89.178 J15.13@106.021,94.615
PD13_SDR_D12: J13.12 J15.12 | length 54.5
  Top Layer w0.254: J13.12@89.605,59.824 87.599,59.824 86.209,61.214 86.209,64.897 93.829,72.517 93.829,78.867 95.48,80.518 95.48,93.218 v1(98.147,95.885)
  Bottom Layer w0.254: v1(98.147,95.885) 98.655,95.885 107.291,95.885 J15.12@108.561,97.155
PD14_SDR_D13: J13.11 J15.11 J16.18 | length 130.1
  Top Layer w0.254: v1(67.183,60.325) 67.183,55.245 68.58,53.848 68.58,23.876 69.342,23.114 69.342,3.072 J16.18@68.048,1.778 ; v1(92.075,59.817) 92.082,59.824 J13.11@94.005,59.824 95.384,59.824 97.917,62.357 97.917,76.2 100.025,78.308 100.025,89.738 104.775,94.488 104.775,95.909 J15.11@106.021,97.155
  Bottom Layer w0.254: v1(67.183,60.325) 80.518,60.325 80.899,59.944 91.948,59.944 v1(92.075,59.817)
PD15_SDR_D14: J13.10 J15.10 J16.17 | length 133.5
  Top Layer w0.254: v1(66.294,60.96) 66.294,55.372 68.048,53.618 J16.17@68.048,4.318 J16.17@68.072,4.342 ; J13.10@89.605,60.624 v1(87.712,60.624) 86.741,61.595 86.741,64.643 94.361,72.263 94.361,78.613 96.139,80.391 96.139,92.837 100.203,96.901 v1(100.203,98.425)
  Bottom Layer w0.254: v1(66.294,60.96) 87.376,60.96 v1(87.712,60.624) ; v1(100.203,98.425) 107.291,98.425 J15.10@108.561,99.695
PE0: J12.55 J14.55 | length 28.2
  Top Layer w0.254: J12.55@44.005,42.224 45.66,42.224 v1(47.879,40.005)
  Bottom Layer w0.254: J14.55@24.995,41.275 26.265,40.005 v1(47.879,40.005)
PE1: J12.56 J14.56 | length 12.5
  Top Layer w0.254: J14.56@27.535,41.275 28.575,41.275 29.524,42.224 J12.56@39.605,42.224
PE2_CTP_INT: J12.63 J14.63 J16.27 | length 95.5
  Top Layer w0.254: J12.63@44.005,39.024 46.193,39.024 50.038,35.179 v1(50.038,32.385) ; J16.27@80.748,4.318 81.28,4.85 v1(81.28,32.385)
  Bottom Layer w0.254: J14.63@24.995,31.115 26.265,32.385 v1(50.038,32.385) v1(81.28,32.385)
PE3_LCD_RST: J12.64 J14.64 J16.2 | length 68.9
  Top Layer w0.254: J14.64@27.535,31.115 28.956,32.536 28.956,35.687 32.293,39.024 J12.64@39.605,39.024 39.64,38.989 v1(41.529,38.989) ; J16.2@47.728,1.778 48.387,1.778 49.022,2.413 49.022,26.162 51.919,29.059 v1(51.919,38.989)
  Bottom Layer w0.254: v1(41.529,38.989) v1(51.919,38.989)
PE4_DCMI_D4: J1.10 J12.65 J14.65 | length 153.2
  Top Layer w0.254: J12.65@44.005,38.224 46.104,38.224 v1(47.498,36.83) 49.403,34.925 49.403,29.591 v1(48.514,28.702) ; J1.10@51.308,124.079 52.578,122.809 v1(52.578,89.662) ; v1(61.468,36.703) 61.468,47.879 62.992,49.403 62.992,51.816 64.643,53.467 v1(64.643,89.662)
  Bottom Layer w0.254: J14.65@24.995,28.575 26.265,29.845 37.973,29.845 39.116,28.702 v1(48.514,28.702) ; v1(47.498,36.83) 61.341,36.83 v1(61.468,36.703) ; v1(52.578,89.662) v1(64.643,89.662)
PE5_DCMI_D6: J1.14 J12.66 J14.66 | length 143.6
  Top Layer w0.254: J14.66@27.535,28.575 29.591,30.631 29.591,35.433 32.382,38.224 J12.66@39.605,38.224 41.399,38.224 v1(41.402,38.227) ; J1.14@46.228,124.079 46.228,123.825 47.498,122.555 47.498,111.252 48.133,110.617 v1(48.133,89.027) ; v1(60.833,38.227) 60.833,48.26 62.357,49.784 62.357,52.07 63.754,53.467 v1(63.754,89.027)
  Bottom Layer w0.254: v1(41.402,38.227) v1(60.833,38.227) ; v1(48.133,89.027) v1(63.754,89.027)
PE6_DCMI_D7: J1.16 J12.67 J14.67 | length 160.3
  Top Layer w0.254: J1.16@43.688,124.079 44.958,122.809 44.958,112.268 47.117,110.109 v1(47.117,87.63) ; J12.67@44.005,37.424 46.015,37.424 v1(47.498,35.941) 48.895,34.544 48.895,29.972 v1(46.228,27.305) ; v1(62.23,35.941) 62.23,47.752 63.627,49.149 63.627,51.308 65.532,53.213 v1(65.532,87.63)
  Bottom Layer w0.254: J14.67@24.995,26.035 26.265,27.305 v1(46.228,27.305) ; v1(47.117,87.63) v1(65.532,87.63) ; v1(47.498,35.941) v1(62.23,35.941)
PE7_SMC_D4: J13.41 J15.41 J16.14 | length 93.4
  Top Layer w0.254: J16.14@62.968,1.778 64.262,3.072 64.262,22.352 66.167,24.257 v1(66.167,45.847) ; v1(92.202,47.879) 92.257,47.824 J13.41@94.005,47.824 98.624,47.824 104.369,53.569 104.369,58.014 105.41,59.055 J15.41@106.021,59.055
  Bottom Layer w0.254: v1(66.167,45.847) 89.154,45.847 91.186,47.879 v1(92.202,47.879)
PE8_SMC_D5: J13.40 J15.40 J16.13 | length 114.8
  Top Layer w0.254: J16.13@62.968,4.318 62.968,21.947 65.532,24.511 65.532,47.244 66.04,47.752 v1(66.04,48.641) ; v1(79.121,59.69) 79.121,56.769 87.266,48.624 J13.40@89.605,48.624
  Bottom Layer w0.254: v1(66.04,48.641) v1(87.757,48.641) ; v1(79.121,59.69) 79.375,59.436 91.313,59.436 91.694,59.055 103.632,59.055 104.902,60.325 107.291,60.325 J15.40@108.561,61.595
PE9_SMC_D6: J13.39 J15.39 J16.12 | length 97.1
  Top Layer w0.254: J16.12@60.428,1.778 61.722,3.072 61.722,21.463 64.897,24.638 v1(64.897,46.482) ; v1(92.202,48.641) 92.219,48.624 J13.39@94.005,48.624 98.408,48.624 103.886,54.102 103.886,58.293 104.98,59.387 104.98,59.895 106.021,60.936 J15.39@106.021,61.595
  Bottom Layer w0.254: v1(64.897,46.482) 88.9,46.482 91.059,48.641 v1(92.202,48.641)
PE10_SMC_D7: J13.38 J15.38 J16.11 | length 117.8
  Top Layer w0.254: J16.11@60.428,4.318 60.706,4.596 60.706,21.209 64.262,24.765 64.262,46.863 65.151,47.752 v1(65.151,49.403) ; v1(79.756,62.865) 79.756,57.023 87.355,49.424 J13.38@89.605,49.424
  Bottom Layer w0.254: v1(65.151,49.403) v1(87.757,49.403) ; v1(79.756,62.865) 107.291,62.865 J15.38@108.561,64.135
